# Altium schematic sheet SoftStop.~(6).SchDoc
size A
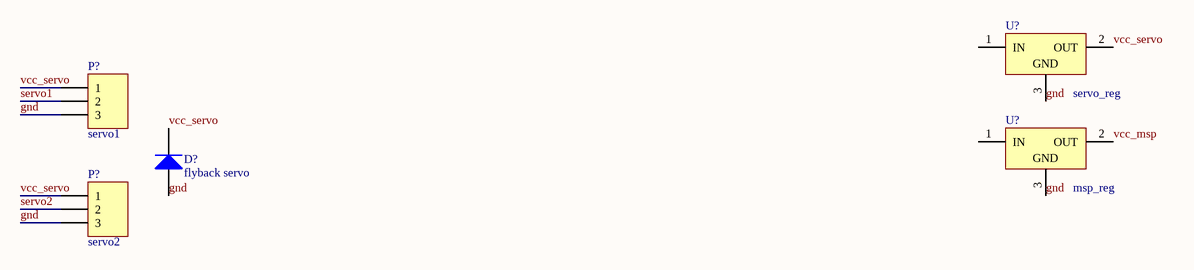
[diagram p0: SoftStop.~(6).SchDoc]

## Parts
(Parts that share a designator on the sheet are numbered #1, #2 ... from top to bottom, then left to right.)
D?  flyback servo  [DO-41]
P?#1  servo1  [HDR1X3H]
P?#2  servo2  [HDR1X3H]
U?#1  servo_reg  [TO220ABN]
U?#2  msp_reg  [TO220ABN]

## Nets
gnd: D?.1(A) P?#1.3 P?#2.3 U?#1.3(GND) U?#2.3(GND)
servo1: P?#1.2
servo2: P?#2.2
vcc_msp: U?#2.2(OUT)
vcc_servo: D?.2(K) P?#1.1 P?#2.1 U?#1.2(OUT)

Not connected (* = marked no-connect by the designer): U?#1 1(IN); U?#2 1(IN)

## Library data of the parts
D? = Diode 1N4001: 1 Amp General Purpose Rectifier
P?#1 P?#2 = Header 3H: Header, 3-Pin, Right Angle
U?#1 U?#2 = L7805CV: Positive Voltage Regulator; Note: Tab is connected to pin 3 (GND).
